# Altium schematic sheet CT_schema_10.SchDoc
size 387 x 278 mm
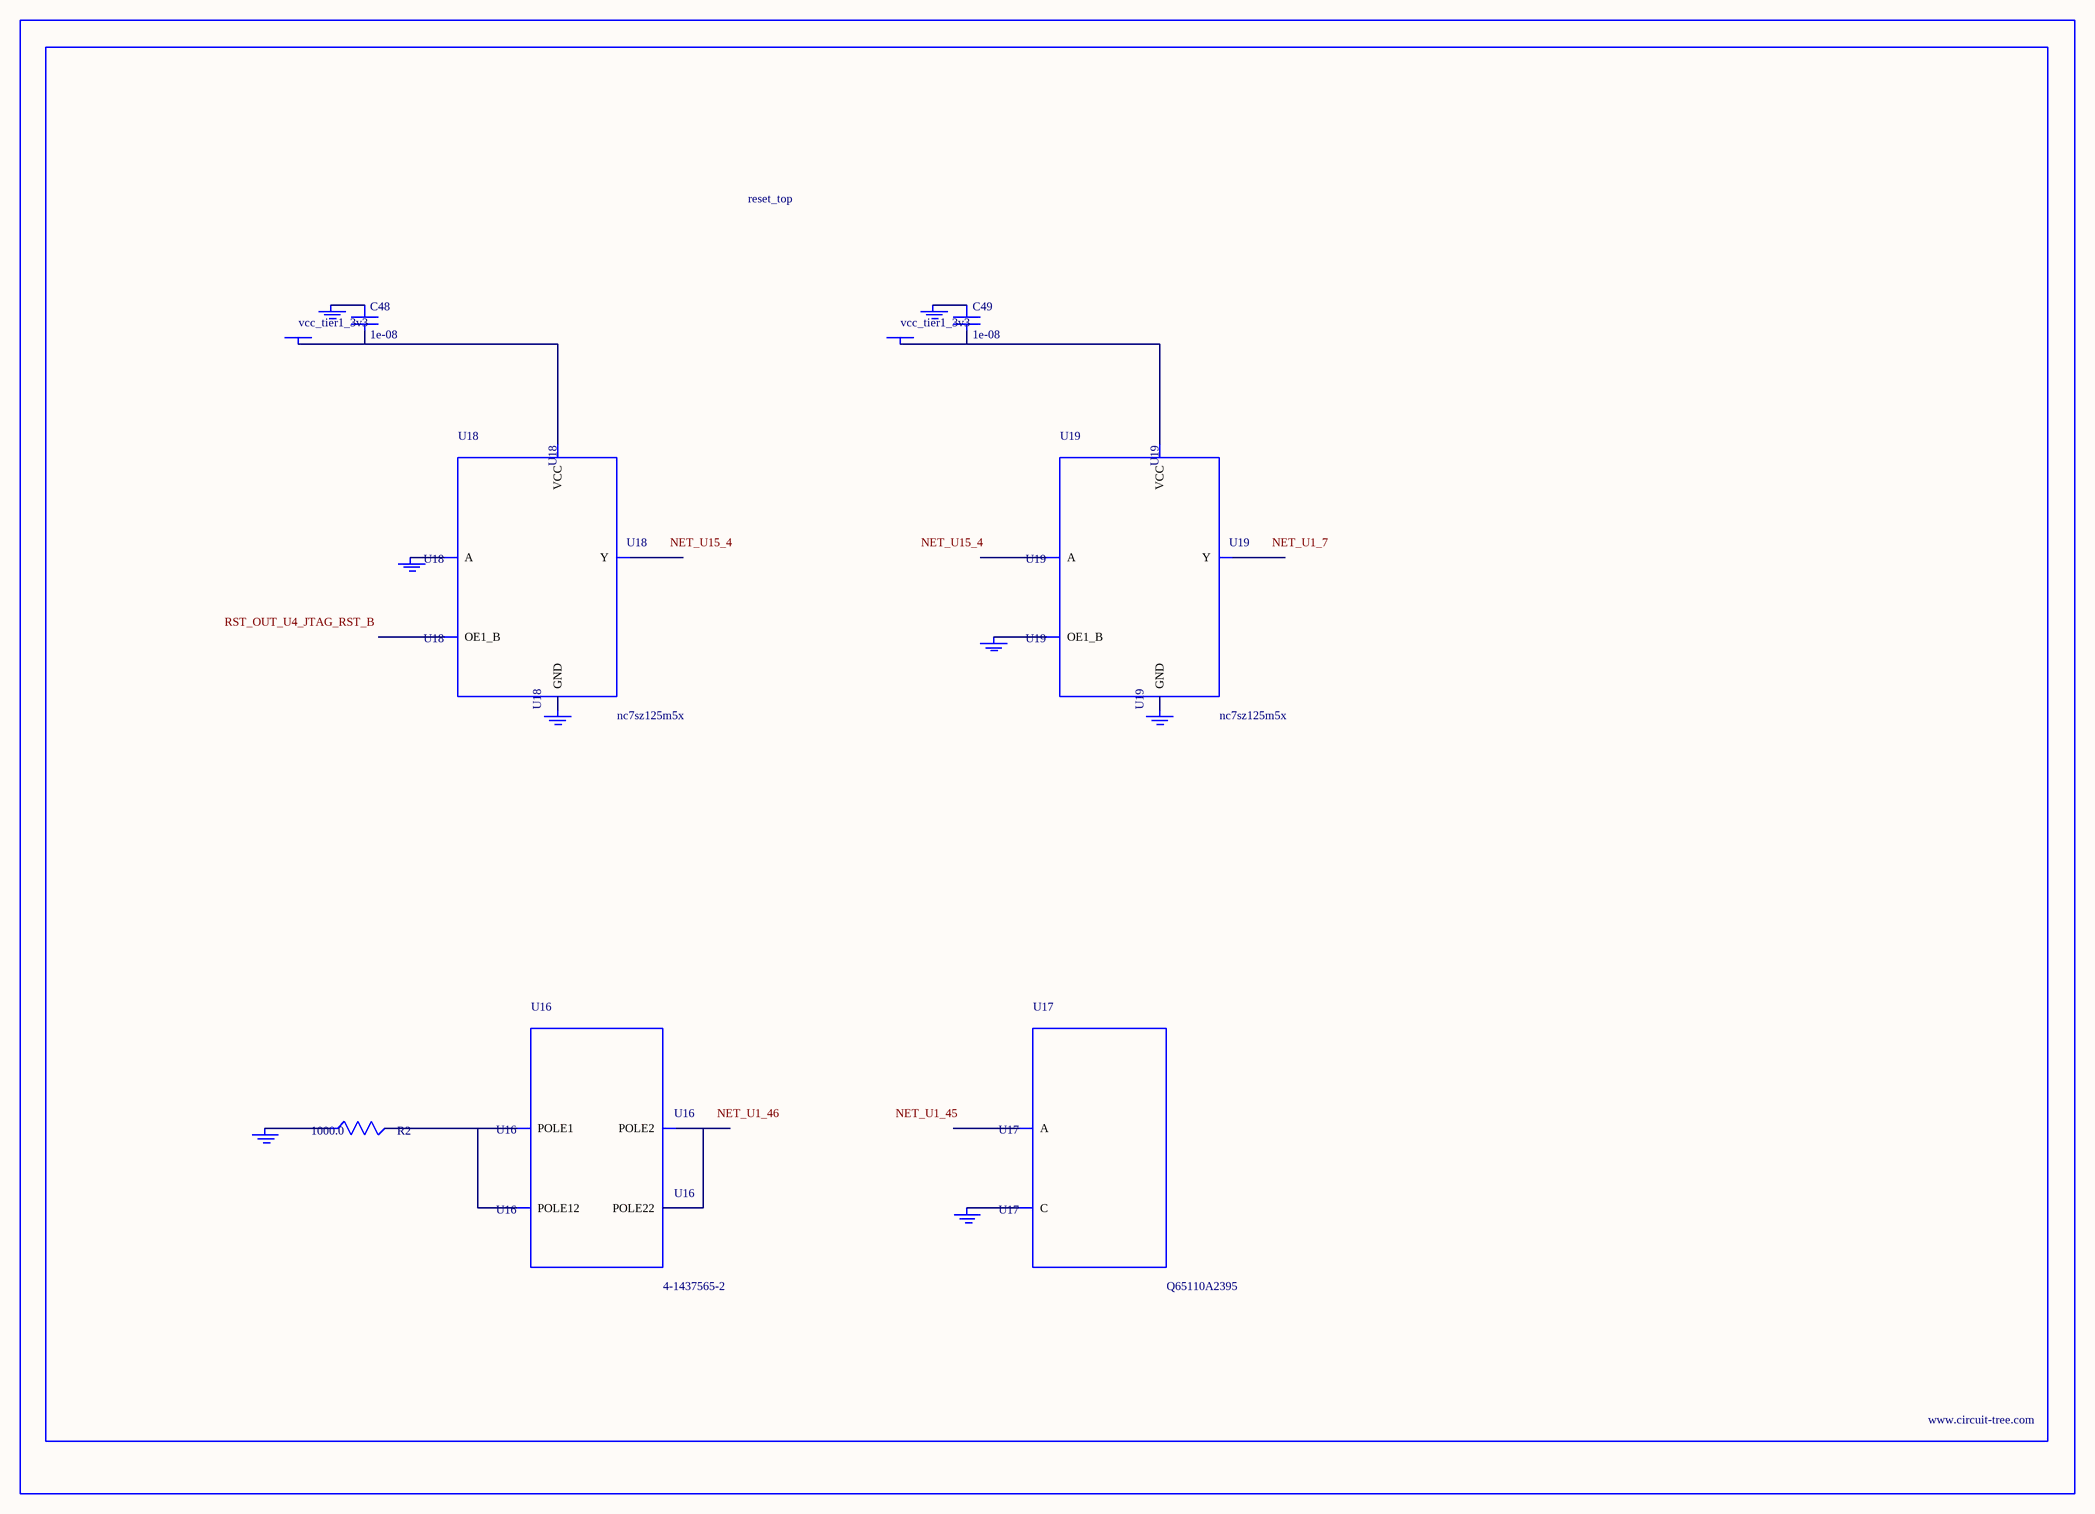
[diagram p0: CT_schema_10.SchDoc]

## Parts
BORDER9  (no value)
C48  1e-08  [C0402]
C49  1e-08  [C0402]
GND_INSTANCE_9_0  (no value)
GND_INSTANCE_9_1  (no value)
GND_INSTANCE_9_2  (no value)
GND_INSTANCE_9_3  (no value)
GND_INSTANCE_9_4  (no value)
GND_INSTANCE_9_5  (no value)
GND_INSTANCE_9_6  (no value)
GND_INSTANCE_9_7  (no value)
POWER_INSTANCE_9_0  vcc_tier1_3v3
POWER_INSTANCE_9_1  vcc_tier1_3v3
R2  1000.0  [R0603]
U16  4-1437565-2  [SW_4-1437565-2]
U17  Q65110A2395  [LGM67K-G1J2-24-Z]
U18  nc7sz125m5x  [NC7SZ125M5X]
U19  nc7sz125m5x  [NC7SZ125M5X]

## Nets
NetC48_1: C48.1 GND_INSTANCE_9_2.0(GND)
NetC48_2: C48.2 POWER_INSTANCE_9_0.0(PWR) U18.5(VCC)
NetC49_1: C49.1 GND_INSTANCE_9_5.0(GND)
NetC49_2: C49.2 POWER_INSTANCE_9_1.0(PWR) U19.5(VCC)
NetGND_INSTANCE_9_0_0: GND_INSTANCE_9_0.0(GND) R2.1
NetGND_INSTANCE_9_1_0: GND_INSTANCE_9_1.0(GND) U17.C
NetGND_INSTANCE_9_3_0: GND_INSTANCE_9_3.0(GND) U18.2(A)
NetGND_INSTANCE_9_4_0: GND_INSTANCE_9_4.0(GND) U18.3(GND)
NetGND_INSTANCE_9_6_0: GND_INSTANCE_9_6.0(GND) U19.1(OE1_B)
NetGND_INSTANCE_9_7_0: GND_INSTANCE_9_7.0(GND) U19.3(GND)
NetR2_2: R2.2 U16.1(POLE1) U16.2(POLE12)
NetU16_3: U16.3(POLE2) U16.4(POLE22)

Not connected (* = marked no-connect by the designer): U17 A; U18 1(OE1_B) 4(Y); U19 2(A) 4(Y)

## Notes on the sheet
- Labels drawn without touching a wire or pin: NET_U1_7, NET_U1_45, NET_U1_46, NET_U15_4, RST_OUT_U4_JTAG_RST_B

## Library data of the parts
BORDER9 = BORDER_PAGE9
C48 C49 = C0402C103K3RAC
GND_INSTANCE_9_0-GND_INSTANCE_9_7 = GND
POWER_INSTANCE_9_0 POWER_INSTANCE_9_1 = PWR
R2 = RC0603JR-071KL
